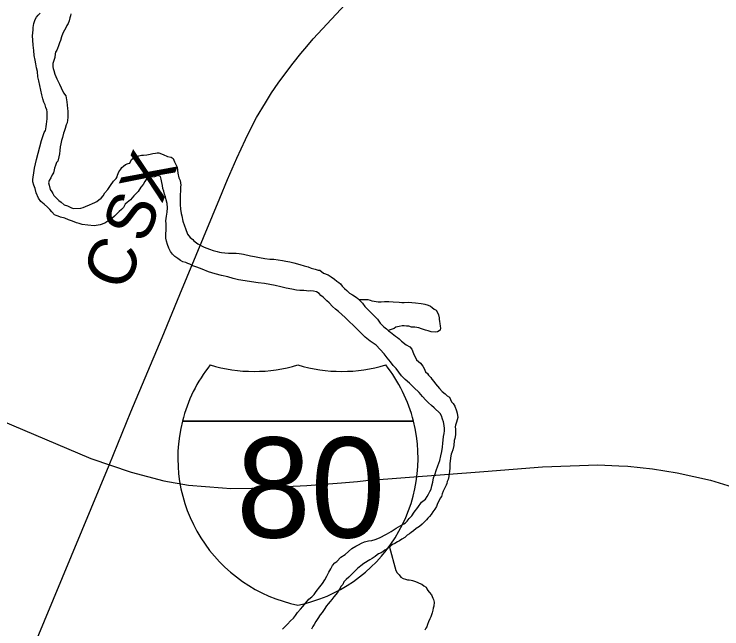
# Model space of a CAD drawing. Extents: x 2010165 to 2382125, y 1060529 to 1407316.
# Drawn here: x 2147994 to 2152412, y 1217333 to 1221171 of the extents above; entities that cross this region are included whole.
import ezdxf

# ---------------------------------------------------------------- set-up
doc = ezdxf.new("R2010")
doc.units = 0
for name, color, linetype in [('GM_X_Interstate_Location', 7, 'Continuous'), ('GM_X_Interstate_Route', 7, 'Continuous'), ('GM_X_Interstate_Shield', 7, 'Continuous'), ('GM_X_Major_River', 7, 'Continuous'), ('GM_X_Minor_River', 7, 'Continuous'), ('GM_X_Rail_Line', 7, 'Continuous'), ('GM_X_Rail_Line_Text', 7, 'Continuous')]:
    doc.layers.add(name, color=color, linetype=linetype)

msp = doc.modelspace()

# ---------------------------------------------------------------- linework, layer by layer
at = {"layer": 'GM_X_Interstate_Route'}
msp.add_lwpolyline([(2147908.1, 1218635.5), (2148474, 1218397.2), (2148724.7, 1218311.5), (2148928.4, 1218258.3), (2149082.4, 1218230.2), (2149294.1, 1218213.5), (2149346.2, 1218210.5), (2149477.1, 1218211.3), (2149610.1, 1218215.8), (2149693.5, 1218223), (2149821.6, 1218228.3), (2149902.3, 1218234.3), (2150037.9, 1218244.8), (2150137.3, 1218252.5), (2150189.5, 1218260.2), (2150925.4, 1218316.6), (2151293.4, 1218344.8), (2151638.5, 1218356.5), (2151768.6, 1218352), (2151826.4, 1218348.6), (2151980.3, 1218332.1), (2152134.4, 1218307.3), (2152340.8, 1218261.4), (2152530, 1218202.9)], dxfattribs=at)
at = {"layer": 'GM_X_Interstate_Shield'}
for p, q in [((2149044.5, 1218629.8), (2150487.3, 1218629.8)), ((2150487.3, 1218629.8), (2149044.5, 1218629.8)), ((2150487.3, 1218629.8), (2149044.5, 1218629.8))]:
    msp.add_line(p, q, dxfattribs=at)
for centre, start, end in [((2149953.4, 1218400), 141.669, 165.8066), ((2149492, 1219878), 253.0091, 286.9909), ((2150039.9, 1219878), 253.0091, 286.9909), ((2149578.4, 1218400), 14.1934, 38.331), ((2149953.4, 1218400), 165.8066, 258.463), ((2149578.4, 1218400), 281.537, 14.1934)]:
    msp.add_arc(centre, 937.5, start, end, dxfattribs=at)
at = {"layer": 'GM_X_Major_River'}
for points in [[(2148112.9, 1221086.8), (2148114.7, 1221100.9), (2148116.5, 1221112.9), (2148120.4, 1221125), (2148126.2, 1221137.1), (2148134.1, 1221151.3), (2148143.9, 1221165.4), (2148155.7, 1221177.6)], [(2148348.1, 1221174), (2148346.3, 1221159.9), (2148342.5, 1221147.8), (2148336.7, 1221129.7), (2148330.9, 1221113.6), (2148323.1, 1221099.4), (2148319.2, 1221089.3), (2148309.4, 1221071.2), (2148297.6, 1221053), (2148289.9, 1221028.8), (2148284.2, 1221006.6), (2148278.4, 1220992.5), (2148270.6, 1220972.4), (2148264.8, 1220956.2), (2148261, 1220946.2), (2148253.1, 1220934), (2148251.2, 1220924), (2148247.5, 1220899.8), (2148239.8, 1220875.7), (2148236, 1220863.6), (2148236.1, 1220853.6), (2148236.3, 1220841.5), (2148238.4, 1220831.5), (2148242.6, 1220819.5), (2148248.9, 1220795.5), (2148261.3, 1220767.6), (2148269.5, 1220751.6), (2148277.8, 1220733.7), (2148288.1, 1220711.7), (2148302.5, 1220679.8), (2148316.8, 1220661.9), (2148323.3, 1220623.9), (2148327.8, 1220581.8), (2148330.1, 1220565.8), (2148330.4, 1220539.7), (2148328.6, 1220525.6), (2148325, 1220493.5), (2148319.2, 1220479.4), (2148313.4, 1220457.2), (2148305.7, 1220439.1), (2148301.8, 1220429), (2148296.1, 1220400.8), (2148290.4, 1220382.7), (2148286.6, 1220360.6), (2148280.9, 1220342.5), (2148279.2, 1220320.4), (2148277.4, 1220298.3), (2148273.7, 1220280.2), (2148268, 1220254), (2148258.1, 1220245.9), (2148252.4, 1220225.7), (2148246.6, 1220209.6)], [(2148941.2, 1219796.8), (2148942.8, 1219824.9), (2148942.5, 1219844.9), (2148942.3, 1219861), (2148942.1, 1219881.1), (2148945.7, 1219909.2), (2148949.4, 1219935.3), (2148951, 1219961.4), (2148948.7, 1219989.5), (2148942.4, 1220011.5), (2148938.1, 1220029.5), (2148933.9, 1220047.5), (2148929.6, 1220065.5), (2148923.4, 1220083.5), (2148921.2, 1220101.5), (2148916.9, 1220119.5), (2148912.6, 1220141.5), (2148908.4, 1220157.5), (2148894.3, 1220163.4), (2148870.4, 1220155.1), (2148826.3, 1220150.5), (2148810.6, 1220126.2), (2148798.8, 1220108), (2148785, 1220091.8), (2148769.4, 1220063.5), (2148741.7, 1220037.1), (2148720, 1220010.8), (2148700.2, 1219994.5), (2148688.3, 1219984.3), (2148676.5, 1219964.1), (2148664.7, 1219951.9), (2148650.8, 1219939.7), (2148636.9, 1219927.5), (2148621.1, 1219909.2), (2148603.3, 1219895), (2148579.5, 1219878.6), (2148559.6, 1219866.3), (2148531.7, 1219856), (2148493.7, 1219849.5), (2148453.6, 1219853), (2148419.4, 1219858.6), (2148399.3, 1219864.4), (2148383.3, 1219868.2), (2148369.2, 1219874), (2148353.1, 1219879.8), (2148332.9, 1219887.6), (2148310.7, 1219897.4), (2148284.6, 1219903.1), (2148268.5, 1219908.9), (2148256.4, 1219914.8), (2148246.4, 1219918.7), (2148230.1, 1219936.5), (2148217.9, 1219950.4), (2148201.7, 1219966.3), (2148181.4, 1219984.1), (2148161.1, 1220001.9), (2148146.8, 1220021.8), (2148132.4, 1220055.7), (2148126, 1220081.7), (2148117.7, 1220103.7), (2148111.4, 1220123.7), (2148111.3, 1220137.7), (2148113.1, 1220153.8), (2148116.7, 1220179.9), (2148122.3, 1220210.1), (2148128, 1220236.2), (2148133.6, 1220264.4), (2148164.2, 1220381.2), (2148173.8, 1220407.4), (2148181.5, 1220431.5), (2148189.4, 1220443.7), (2148191.3, 1220453.7), (2148195.1, 1220469.8), (2148196.9, 1220483.9), (2148198.7, 1220500), (2148200.4, 1220518), (2148200.2, 1220534.1), (2148200.1, 1220544.1), (2148199.9, 1220560.2), (2148197.7, 1220574.2), (2148191.5, 1220588.1), (2148187.3, 1220604.2), (2148179, 1220622.1), (2148172.8, 1220642.1), (2148166.4, 1220668.1), (2148160, 1220696.1), (2148153.6, 1220726.1), (2148149.3, 1220754.2), (2148142.9, 1220780.2), (2148140.5, 1220812.2), (2148134.2, 1220836.3), (2148129.9, 1220860.3), (2148125.5, 1220884.3), (2148119.1, 1220912.3), (2148116.7, 1220944.4), (2148112.3, 1220976.4), (2148109.9, 1221008.5), (2148109.5, 1221036.6), (2148111.3, 1221054.7), (2148113, 1221072.8), (2148112.9, 1221086.8)], [(2148246.6, 1220209.6), (2148244.7, 1220199.6), (2148238.9, 1220181.4), (2148231.1, 1220167.3), (2148223.3, 1220149.1), (2148213.5, 1220133), (2148209.7, 1220118.9), (2148211.9, 1220102.8), (2148218.2, 1220076.8), (2148228.5, 1220060.9), (2148236.6, 1220051), (2148242.8, 1220039), (2148252.9, 1220029.1), (2148263.1, 1220017.2), (2148273.2, 1220007.3), (2148287.4, 1219997.4), (2148305.6, 1219981.6), (2148327.8, 1219973.8), (2148347.9, 1219964.1), (2148362, 1219958.2), (2148410.1, 1219960.8), (2148426.1, 1219963), (2148440, 1219969.2), (2148463.9, 1219981.5), (2148483.8, 1219989.8), (2148497.8, 1219996), (2148509.7, 1220002.2), (2148523.6, 1220012.4), (2148537.5, 1220022.6), (2148549.3, 1220036.8), (2148561.1, 1220054.9), (2148578.9, 1220077.2), (2148596.6, 1220101.5), (2148614.3, 1220127.8), (2148630.1, 1220144.1), (2148637.9, 1220156.2), (2148639.8, 1220166.3), (2148647.6, 1220186.4), (2148659.4, 1220202.6), (2148667.3, 1220212.8), (2148677.1, 1220222.9), (2148689, 1220233.1), (2148707, 1220239.3), (2148717, 1220241.5), (2148726.7, 1220263.7), (2148746.5, 1220277.9), (2148772.5, 1220286.3), (2148788.4, 1220290.5), (2148802.5, 1220290.7), (2148822.5, 1220292.9), (2148842.5, 1220297.2), (2148860.4, 1220301.4), (2148876.4, 1220303.6), (2148886.4, 1220305.8), (2148898.4, 1220305.9), (2148924.6, 1220294.2), (2148950.8, 1220282.5), (2148974.9, 1220278.7), (2148987.1, 1220268.9), (2148995.4, 1220248.9), (2149005.6, 1220228.9), (2149011.8, 1220215), (2149016.3, 1220178.9), (2149022.7, 1220148.9), (2149030.9, 1220133), (2149035.3, 1220102.9), (2149033.5, 1220092.9), (2149033.6, 1220078.8), (2149031.9, 1220062.8), (2149030.1, 1220046.7), (2149030.4, 1220018.6), (2149030.7, 1219998.5), (2149030.9, 1219982.5), (2149033.3, 1219954.4), (2149037.6, 1219926.4), (2149041.8, 1219912.4), (2149046.3, 1219878.3), (2149056.7, 1219850.4), (2149064.9, 1219832.4), (2149077.4, 1219798.4), (2149093.7, 1219776.6), (2149109.9, 1219764.7), (2149116, 1219754.8), (2149140.3, 1219737), (2149180.6, 1219715.4), (2149212.9, 1219703.8), (2149237, 1219696.1), (2149261.1, 1219688.3), (2149275.2, 1219684.5), (2149289.3, 1219682.7), (2149309.3, 1219680.9), (2149333.4, 1219679.2), (2149359.4, 1219679.5), (2149379.5, 1219677.8), (2149399.5, 1219676), (2149413.6, 1219674.2), (2149425.6, 1219672.3), (2149469.8, 1219662.8), (2149494, 1219657.1), (2149526.1, 1219651.5), (2149560.2, 1219645.9)], [(2150514.2, 1218090.5), (2150537.8, 1218124.9), (2150561.6, 1218143.3), (2150573.4, 1218159.5), (2150581.2, 1218173.6), (2150589, 1218189.8), (2150596.8, 1218205.9), (2150602.6, 1218226), (2150608.3, 1218248.2), (2150611.9, 1218276.3), (2150621.7, 1218300.5), (2150629.4, 1218322.7), (2150639, 1218350.9), (2150652.6, 1218385.2), (2150658.2, 1218413.3), (2150663.9, 1218439.5), (2150667.5, 1218467.6), (2150671.2, 1218491.7), (2150673, 1218511.8), (2150674.7, 1218533.9), (2150678.5, 1218552), (2150680.2, 1218570.1), (2150680, 1218584.1), (2150677.8, 1218602.2), (2150675.5, 1218626.2), (2150669.3, 1218642.2), (2150663, 1218662.2), (2150652.8, 1218678.1), (2150616.2, 1218713.8), (2150600, 1218727.6), (2150581.8, 1218743.5), (2150563.5, 1218761.3), (2150543.2, 1218783.1), (2150522.8, 1218808.9), (2150490.4, 1218840.6), (2150462, 1218866.4), (2150435.6, 1218890.1), (2150413.3, 1218913.9), (2150395, 1218935.8), (2150378.6, 1218957.7), (2150360.3, 1218977.5), (2150344, 1218999.4), (2150323.7, 1219025.2), (2150303.3, 1219051), (2150278.9, 1219076.8), (2150254.5, 1219104.6), (2150216.1, 1219130.2), (2150185.7, 1219153.9), (2150161.4, 1219179.7), (2150137, 1219201.5), (2150112.6, 1219227.3), (2150086.3, 1219253), (2150059.9, 1219276.8), (2150039.6, 1219296.6), (2150019.4, 1219314.4), (2150001.1, 1219330.2), (2149980.9, 1219346.1), (2149960.6, 1219367.9), (2149946.3, 1219381.7), (2149936.2, 1219391.6), (2149924, 1219403.5), (2149909.8, 1219415.4), (2149897.7, 1219427.3), (2149881.5, 1219437.1), (2149863.4, 1219440.9), (2149847.4, 1219442.7), (2149833.4, 1219442.6), (2149819.3, 1219444.4), (2149803.2, 1219446.2), (2149777.2, 1219445.9), (2149757.2, 1219447.6), (2149727, 1219453.3), (2149692.9, 1219460.9), (2149658.7, 1219468.5), (2149624.5, 1219476.1), (2149590.4, 1219483.7), (2149556.3, 1219489.3), (2149518.1, 1219492.8), (2149395.7, 1219511.4), (2149361.5, 1219521), (2149327.3, 1219530.6), (2149289.1, 1219540.2), (2149248.9, 1219549.8), (2149206.7, 1219563.3), (2149168.4, 1219578.9), (2149134.2, 1219590.5), (2149110, 1219600.2), (2149091.9, 1219610), (2149077.8, 1219613.9), (2149065.7, 1219619.7), (2149047.6, 1219625.5), (2149033.5, 1219633.4), (2149015.3, 1219645.2), (2148997.1, 1219657), (2148982.9, 1219672.9), (2148970.6, 1219688.8), (2148960.3, 1219710.7), (2148952, 1219732.7), (2148945.7, 1219752.7), (2148941.5, 1219772.7), (2148941.2, 1219796.8)], [(2149560.2, 1219645.9), (2149590.3, 1219642.2), (2149616.4, 1219640.5), (2149642.5, 1219636.8), (2149668.6, 1219633.1), (2149690.7, 1219629.4), (2149714.8, 1219623.7), (2149740.9, 1219618), (2149777.1, 1219608.4), (2149805.2, 1219600.7), (2149829.4, 1219593), (2149849.5, 1219585.2), (2149873.6, 1219579.5), (2149891.7, 1219573.7), (2149901.8, 1219571.8), (2149926.1, 1219554.1), (2149954.2, 1219544.4), (2149972.4, 1219530.5), (2149994.7, 1219516.8), (2150008.8, 1219504.9), (2150021, 1219495), (2150031.1, 1219487.1), (2150041.3, 1219473.2), (2150057.6, 1219457.3), (2150071.7, 1219445.5), (2150088, 1219429.6), (2150106.1, 1219417.8), (2150128.4, 1219404), (2150140.5, 1219396.1), (2150150.6, 1219386.3), (2150168.9, 1219366.4), (2150183.2, 1219346.5), (2150199.5, 1219328.7), (2150217.7, 1219312.8), (2150231.9, 1219299), (2150246.2, 1219283.1), (2150262.4, 1219267.2), (2150278.8, 1219241.3), (2150303.1, 1219219.6), (2150319.3, 1219205.7), (2150331.5, 1219193.8), (2150343.6, 1219186), (2150376, 1219160.3), (2150388.1, 1219152.4), (2150398.2, 1219144.5), (2150412.5, 1219128.6), (2150440.8, 1219106.9), (2150465, 1219093.2), (2150477.2, 1219079.2), (2150487.6, 1219053.3), (2150506.1, 1219013.4), (2150530.5, 1218991.6), (2150544.7, 1218973.7), (2150552.9, 1218957.8), (2150563.2, 1218937.9), (2150575.4, 1218928), (2150581.5, 1218918), (2150595.7, 1218902.1), (2150601.9, 1218892.2), (2150614.1, 1218878.3), (2150624.3, 1218862.4), (2150648.7, 1218834.6), (2150667, 1218814.7), (2150685.2, 1218800.9), (2150697.4, 1218789), (2150711.6, 1218779.1), (2150717.7, 1218765.2), (2150723.9, 1218751.2), (2150734.1, 1218739.3), (2150746.3, 1218723.4), (2150756.8, 1218693.4), (2150760.9, 1218679.4), (2150763.3, 1218653.4), (2150755.7, 1218623.2), (2150749.9, 1218605.1), (2150748, 1218595), (2150750.2, 1218579), (2150750.4, 1218564.9), (2150748.6, 1218546.9), (2150746.8, 1218532.8), (2150745, 1218522.7), (2150741.1, 1218508.6), (2150739.5, 1218478.5), (2150731.9, 1218450.3), (2150726.1, 1218434.2), (2150722.2, 1218424.1), (2150720.3, 1218414.1), (2150715, 1218365.9), (2150713.3, 1218337.8), (2150711.6, 1218315.7), (2150709.8, 1218303.6), (2150708, 1218283.5), (2150704.2, 1218265.4), (2150698.4, 1218253.3), (2150694.6, 1218241.2), (2150690.7, 1218231.1), (2150684.9, 1218217), (2150679, 1218204.9), (2150673.1, 1218192.8), (2150667.3, 1218176.7), (2150661.5, 1218160.6)], [(2150146.5, 1219390.3), (2150202.7, 1219388.9), (2150216.8, 1219385.1), (2150226.8, 1219381.2), (2150240.9, 1219379.3), (2150254.9, 1219377.5), (2150267, 1219375.6), (2150285, 1219375.9), (2150307, 1219376.1), (2150333.1, 1219376.4), (2150361.2, 1219374.8), (2150397.2, 1219373.2), (2150415.3, 1219371.4), (2150429.3, 1219371.6), (2150453.4, 1219371.9), (2150477.4, 1219370.2), (2150499.5, 1219368.5), (2150535.6, 1219364.9), (2150547.6, 1219363), (2150557.7, 1219361.1), (2150579.8, 1219353.4), (2150593.9, 1219347.6), (2150604, 1219339.6), (2150616.2, 1219329.8), (2150628.3, 1219321.9), (2150638.6, 1219304), (2150642.7, 1219294), (2150646.9, 1219276), (2150647.1, 1219265.9), (2150649.3, 1219251.9), (2150651.4, 1219239.9), (2150653.6, 1219223.9), (2150655.8, 1219209.9), (2150654, 1219197.8), (2150638.1, 1219187.6), (2150622.1, 1219185.4), (2150598, 1219187.1), (2150579.9, 1219192.9), (2150561.8, 1219198.7), (2150537.7, 1219206.4), (2150521.6, 1219212.2), (2150507.5, 1219214.1), (2150495.5, 1219215.9), (2150485.4, 1219217.8), (2150475.4, 1219217.7), (2150457.3, 1219223.5), (2150443.3, 1219223.3), (2150429.2, 1219225.1), (2150417.2, 1219225), (2150397.2, 1219220.7), (2150387.2, 1219218.6), (2150377.3, 1219216.5), (2150367.3, 1219208.3), (2150353.4, 1219204.1), (2150329.5, 1219195.8)], [(2150661.5, 1218160.6), (2150653.7, 1218148.4), (2150645.9, 1218130.3), (2150638.1, 1218116.1), (2150630.3, 1218098), (2150620.5, 1218079.8), (2150608.7, 1218063.6), (2150596.9, 1218047.4), (2150587.1, 1218035.2), (2150577.2, 1218025.1), (2150569.3, 1218012.9), (2150555.4, 1218000.8), (2150541.6, 1217986.5), (2150525.8, 1217972.3), (2150503.9, 1217960), (2150488, 1217945.7), (2150472.2, 1217935.5), (2150462.2, 1217927.4), (2150448.4, 1217917.2), (2150432.5, 1217902.9), (2150414.6, 1217892.7), (2150400.7, 1217882.5), (2150386.8, 1217876.3), (2150370.9, 1217866.1), (2150356.9, 1217859.9), (2150347, 1217853.7), (2150337.1, 1217843.6), (2150323.2, 1217833.4), (2150309.3, 1217825.2), (2150297.4, 1217817), (2150285.5, 1217808.8), (2150269.6, 1217800.6), (2150259.6, 1217794.5), (2150247.7, 1217784.3), (2150229.9, 1217772), (2150213.9, 1217763.8), (2150178.2, 1217741.3), (2150158.3, 1217727), (2150138.5, 1217710.7), (2150122.7, 1217694.5), (2150102.9, 1217674.2), (2150083.1, 1217655.8), (2150067.3, 1217641.6), (2150053.4, 1217627.4), (2150045.6, 1217611.2), (2150035.8, 1217599.1), (2150026, 1217580.9), (2150016.2, 1217566.8), (2150002.4, 1217548.5), (2149990.6, 1217532.3), (2149976.8, 1217516.1), (2149966.9, 1217503.9), (2149955.1, 1217489.8), (2149945.2, 1217477.6), (2149929.5, 1217453.3), (2149917.7, 1217435.1), (2149903.9, 1217420.9), (2149890.2, 1217398.7), (2149878.4, 1217378.5), (2149866.6, 1217360.3), (2149858.8, 1217348.1), (2149851, 1217332)], [(2149668.6, 1217331.7), (2149684.5, 1217346), (2149700.3, 1217362.2), (2149720.1, 1217382.5), (2149737.9, 1217400.8), (2149751.7, 1217417), (2149763.5, 1217435.2), (2149781.2, 1217455.5), (2149797, 1217473.8), (2149814.8, 1217496.1), (2149834.5, 1217518.4), (2149852.3, 1217532.6), (2149866.2, 1217546.8), (2149879.9, 1217567.1), (2149903.6, 1217595.5), (2149919.4, 1217615.7), (2149933.1, 1217640), (2149946.8, 1217662.2), (2149958.5, 1217686.4), (2149972.2, 1217708.7), (2149982, 1217728.8), (2149995.8, 1217745.1), (2150007.7, 1217753.2), (2150033.4, 1217781.6), (2150061.2, 1217798.1), (2150081, 1217816.3), (2150102.8, 1217834.7), (2150126.7, 1217849), (2150144.6, 1217857.3), (2150162.5, 1217867.5), (2150182.4, 1217875.8), (2150206.4, 1217882.1), (2150226.4, 1217884.3), (2150248.3, 1217890.6), (2150274.3, 1217901), (2150318, 1217923.6), (2150347.8, 1217942), (2150379.6, 1217962.5), (2150407.5, 1217978.9), (2150427.4, 1217989.1), (2150437.3, 1217995.3), (2150447.2, 1218005.4), (2150461, 1218021.6), (2150476.8, 1218039.9), (2150492.5, 1218062.2), (2150514.2, 1218090.5)]]:
    msp.add_lwpolyline(points, dxfattribs=at)
at = {"layer": 'GM_X_Minor_River'}
msp.add_lwpolyline([(2150337.4, 1217843.8), (2150377.1, 1217697.6), (2150385.3, 1217683.6), (2150397.5, 1217669.7), (2150407.7, 1217655.8), (2150423.8, 1217648), (2150437.9, 1217644.2), (2150450, 1217640.3), (2150460, 1217638.4), (2150472.1, 1217636.6), (2150482.1, 1217634.7), (2150494.2, 1217630.8), (2150510.3, 1217625), (2150522.4, 1217619.1), (2150538.5, 1217611.3), (2150552.7, 1217601.4), (2150566.8, 1217593.6), (2150570.9, 1217583.6), (2150577.1, 1217573.6), (2150585.2, 1217561.7), (2150599.5, 1217545.8), (2150607.7, 1217525.8), (2150611.9, 1217515.9), (2150616.1, 1217499.9), (2150614.4, 1217475.8), (2150610.6, 1217461.7), (2150608.7, 1217449.6), (2150604.9, 1217433.5), (2150599.1, 1217421.4), (2150595.2, 1217409.3), (2150589.4, 1217395.2), (2150581.6, 1217377.1), (2150573.8, 1217360.9), (2150570, 1217346.8), (2150564.1, 1217336.7), (2150558.3, 1217324.6)], dxfattribs=at)
at = {"layer": 'GM_X_Rail_Line'}
msp.add_lwpolyline([(2147722.1, 1216275.4), (2148587.8, 1218354.9), (2148723.4, 1218687.3), (2148919.2, 1219152.6), (2149029.3, 1219420.6), (2149279.1, 1220022), (2149326.9, 1220138.3), (2149384, 1220272.3), (2149438, 1220389.1), (2149471.2, 1220457.2), (2149508.1, 1220525.7), (2149563.2, 1220618.2), (2149601.6, 1220680.5), (2149643.1, 1220741.2), (2149689.9, 1220805.1), (2149735.6, 1220864.8), (2149783.4, 1220924.6), (2149821.8, 1220969.8), (2149861.3, 1221016), (2149918.9, 1221080.4), (2150060.2, 1221232)], dxfattribs=at)

# ---------------------------------------------------------------- texts
at = {"layer": 'GM_X_Interstate_Location'}
for s in ['-', '.', ',']:
    msp.add_text(s, height=1, dxfattribs=at).set_placement((2149765.8, 1218230.9))
msp.add_text('80', height=1, rotation=0, dxfattribs=at).set_placement((2149561.5, 1218023.9))
at = {"layer": 'GM_X_Interstate_Shield'}
msp.add_text('80', height=625, dxfattribs=at).set_placement((2149380.7, 1217903.3))
at = {"layer": 'GM_X_Rail_Line_Text'}
for s, rotation, p in [('X', 67.2879, (2148916.1, 1219982.4)), ('S', 67.5531, (2148812.1, 1219730.8)), ('C', 67.5717, (2148687.9, 1219429.8))]:
    msp.add_text(s, height=299, rotation=rotation, dxfattribs=at).set_placement(p)

doc.saveas('drawing.dxf')
